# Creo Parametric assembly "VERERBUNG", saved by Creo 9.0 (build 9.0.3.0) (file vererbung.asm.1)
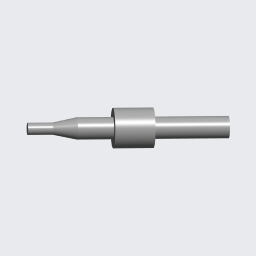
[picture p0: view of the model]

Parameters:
  DATUM = "XX.XX.XX"
  ERSTELLER = "ARINDA"
  TEILETYP = "Montage-Baugruppe"

Other parameters: MASSE

Created from: ARINDA-STARTBAUGRUPPE.ASM

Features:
  1. coordinate system "ACS0"
  2. datum plane "ADTM1", "A_RECHTS_Y-Z"
  3. datum plane "ADTM2", "A_OBEN_X-Z"
  4. datum plane "ADTM3", "A_VORNE_X-Y"
  5. datum axis "AA_1"
  6. datum axis "AA_2"
  7. datum axis "AA_3"
  8. component "ROHTEIL"
  9. component "FERTIGTEIL"
  10. component "FUNKTIONSTEIL"

Other named items: A_BASIS, A_X-ACHSE, A_Y-ACHSE, A_Z-ACHSE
